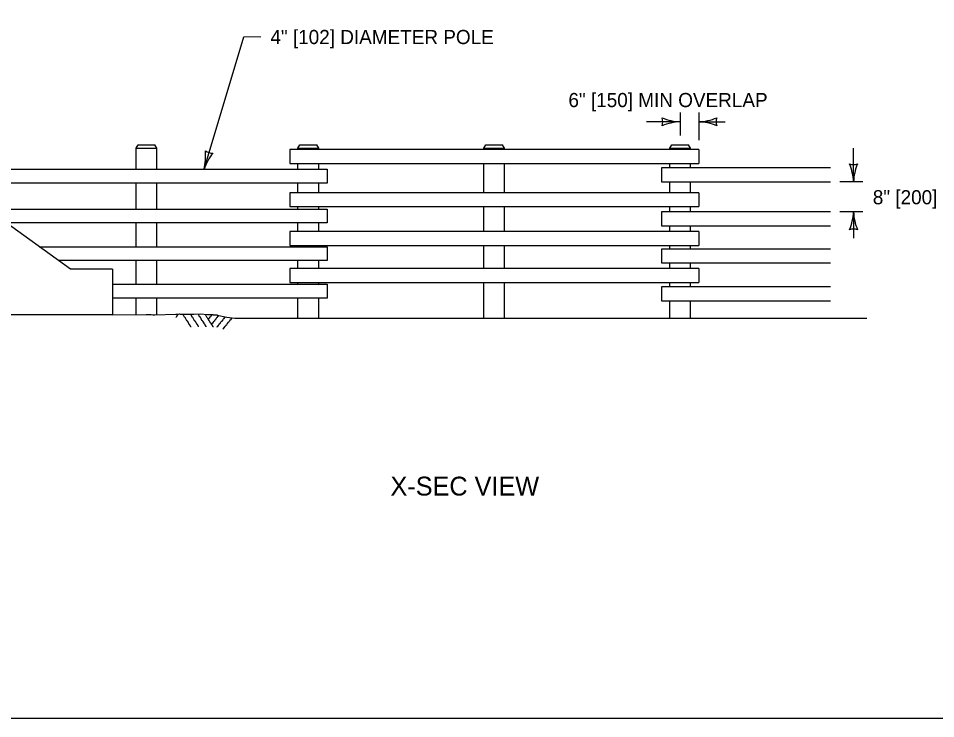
# Model space of a CAD drawing. Extents: x 49991 to 50288, y 49919 to 50011.
# Drawn here: x 50008.695 to 50012.585, y 49987.799 to 49990.769 of the extents above; entities that cross this region are included whole.
import ezdxf

# ---------------------------------------------------------------- set-up
doc = ezdxf.new("R2010")
doc.units = 0
for name, color, linetype in [('Level 1', 7, 'Continuous'), ('Level 2', 7, 'Continuous'), ('Level 3', 7, 'Continuous'), ('Level 5', 7, 'Continuous'), ('Level 7', 7, 'Continuous')]:
    doc.layers.add(name, color=color, linetype=linetype)

msp = doc.modelspace()

# ---------------------------------------------------------------- linework, layer by layer
at = {"layer": 'Level 1'}
for p, q in [((50008.9164, 49989.7045), (50007.5728, 49990.6756)), ((50009.095, 49989.7045), (50008.9164, 49989.7045)), ((50009.095, 49989.7045), (50009.095, 49989.5113)), ((50009.095, 49989.5113), (50007.2424, 49989.5113))]:
    msp.add_line(p, q, dxfattribs=at)
msp.add_lwpolyline([(49999.3835, 49998.9992), (50016.7501, 49998.9992), (50016.7501, 49987.7988), (49999.3835, 49987.7988)], close=True, dxfattribs=at)
msp.add_lwpolyline([(49999.3835, 49998.9992), (50016.7501, 49998.9992), (50016.7501, 49987.7988), (49999.3835, 49987.7988)], close=True, dxfattribs=at)
at = {"layer": 'Level 3'}
for p, q in [((50009.4828, 49990.1289), (50009.6515, 49990.6897)), ((50009.7242, 49990.6896), (50009.6515, 49990.6897)), ((50011.5013, 49990.3701), (50011.5013, 49990.2723)), ((50011.5804, 49990.3701), (50011.5804, 49990.2525)), ((50011.5013, 49990.3301), (50011.3584, 49990.3301)), ((50011.5804, 49990.3301), (50011.6919, 49990.3301)), ((50012.2367, 49990.0755), (50012.2367, 49990.2184)), ((50012.2767, 49990.0755), (50012.1789, 49990.0755)), ((50012.2767, 49989.9482), (50012.1789, 49989.9482)), ((50012.2367, 49989.9482), (50012.2367, 49989.8367))]:
    msp.add_line(p, q, dxfattribs=at)
for centre, radius, start, end in [((50011.5105, 49990.5522), 0.2223, 247.456, 267.6395), ((50011.3731, 49990.3301), 0.0548, 342.1388, 17.8612), ((50011.5128, 49990.0974), 0.233, 92.8273, 112.0772), ((50011.5689, 49990.5628), 0.233, 272.8273, 292.0772), ((50011.5712, 49990.108), 0.2223, 67.456, 87.6395), ((50011.7086, 49990.3301), 0.0548, 162.1388, 197.8612), ((50009.2566, 49990.185), 0.233, 346.0815, 5.3313), ((50009.6929, 49990.0562), 0.2223, 140.7102, 160.8937), ((50009.5197, 49990.2517), 0.0548, 235.393, 271.1153), ((50012.2367, 49990.2037), 0.0548, 252.1388, 287.8612), ((50012.004, 49990.064), 0.233, 2.8273, 22.0772), ((50012.4588, 49990.0663), 0.2223, 157.456, 177.6395), ((50012.0145, 49989.9574), 0.2223, 337.456, 357.6395), ((50012.4694, 49989.9597), 0.233, 182.8273, 202.0772), ((50012.2367, 49989.82), 0.0548, 72.1388, 107.8612)]:
    msp.add_arc(centre, radius, start, end, dxfattribs=at)
at = {"layer": 'Level 5'}
for p, q in [((50009.5112, 49989.5124), (50009.5219, 49989.5124)), ((50009.6129, 49989.4968), (50012.293, 49989.4968))]:
    msp.add_line(p, q, dxfattribs=at)
for points in [[(50009.095, 49989.5113), (50009.2368, 49989.513), (50009.2588, 49989.513), (50009.2655, 49989.5113), (50009.2739, 49989.5113)], [(50009.2739, 49989.5113), (50009.3634, 49989.5146), (50009.3736, 49989.5146), (50009.3786, 49989.5163), (50009.382, 49989.5146), (50009.4343, 49989.5146), (50009.4394, 49989.5146), (50009.4681, 49989.5163), (50009.4968, 49989.513), (50009.5154, 49989.513), (50009.5204, 49989.5113), (50009.5322, 49989.5113), (50009.539, 49989.5113), (50009.539, 49989.5096), (50009.5795, 49989.5011), (50009.6129, 49989.4968)], [(50009.371, 49989.5151), (50009.3727, 49989.5134), (50009.3677, 49989.5066), (50009.3677, 49989.5049), (50009.366, 49989.5049), (50009.3643, 49989.5016), (50009.3631, 49989.5004)], [(50009.3934, 49989.5146), (50009.3985, 49989.5028), (50009.4018, 49989.5011), (50009.4086, 49989.4876), (50009.4103, 49989.4876), (50009.412, 49989.4842), (50009.412, 49989.4826), (50009.4153, 49989.4792), (50009.4187, 49989.4724), (50009.4204, 49989.4724), (50009.4255, 49989.4623), (50009.4289, 49989.4623)], [(50009.4259, 49989.5151), (50009.4309, 49989.5032), (50009.4343, 49989.5016), (50009.4411, 49989.488), (50009.4428, 49989.488), (50009.4445, 49989.4847), (50009.4445, 49989.483), (50009.4478, 49989.4796), (50009.4512, 49989.4729), (50009.4529, 49989.4729), (50009.458, 49989.4627), (50009.4614, 49989.4627)], [(50009.4576, 49989.5159), (50009.4626, 49989.5041), (50009.466, 49989.5024), (50009.4727, 49989.4889), (50009.4744, 49989.4889), (50009.4761, 49989.4855), (50009.4761, 49989.4839), (50009.4795, 49989.4805), (50009.4829, 49989.4737), (50009.4846, 49989.4737), (50009.4896, 49989.4636), (50009.493, 49989.4636)], [(50009.4875, 49989.5142), (50009.4926, 49989.5024), (50009.496, 49989.5007), (50009.5027, 49989.4872), (50009.5044, 49989.4872), (50009.5061, 49989.4839), (50009.5061, 49989.4821), (50009.5095, 49989.4788), (50009.5129, 49989.472), (50009.5145, 49989.472), (50009.5196, 49989.4619), (50009.523, 49989.4619)], [(50009.5159, 49989.5109), (50009.5129, 49989.5079), (50009.5129, 49989.5062), (50009.5111, 49989.5062), (50009.5095, 49989.5029), (50009.5078, 49989.5029), (50009.5078, 49989.5011), (50009.5044, 49989.4978), (50009.5044, 49989.4961), (50009.5027, 49989.4961), (50009.501, 49989.4927)], [(50009.5433, 49989.5068), (50009.542, 49989.5054), (50009.542, 49989.5037), (50009.5403, 49989.5037), (50009.5386, 49989.5003), (50009.5352, 49989.4986), (50009.5335, 49989.4935), (50009.5301, 49989.4919), (50009.5301, 49989.4902), (50009.5267, 49989.4868), (50009.5267, 49989.4851), (50009.5251, 49989.4851), (50009.5234, 49989.4818), (50009.5217, 49989.4818), (50009.5217, 49989.4801), (50009.5183, 49989.4767), (50009.5183, 49989.475), (50009.5166, 49989.475), (50009.5149, 49989.4716)], [(50009.5694, 49989.5032), (50009.5711, 49989.5016), (50009.566, 49989.4948), (50009.566, 49989.4931), (50009.5643, 49989.4931), (50009.5626, 49989.4897), (50009.5576, 49989.4847), (50009.5576, 49989.483), (50009.5559, 49989.483), (50009.5542, 49989.4796), (50009.5508, 49989.4779), (50009.5491, 49989.4729), (50009.5457, 49989.4712), (50009.5457, 49989.4695), (50009.5424, 49989.4661), (50009.5424, 49989.4644), (50009.5407, 49989.4644), (50009.539, 49989.4611), (50009.5373, 49989.4611), (50009.5373, 49989.4594), (50009.5368, 49989.4588)], [(50009.5977, 49989.4986), (50009.5994, 49989.4969), (50009.5943, 49989.4902), (50009.5943, 49989.4885), (50009.5926, 49989.4885), (50009.5909, 49989.4851), (50009.5858, 49989.4801), (50009.5858, 49989.4783), (50009.5842, 49989.4783), (50009.5825, 49989.475), (50009.5791, 49989.4733), (50009.5774, 49989.4682), (50009.574, 49989.4665), (50009.574, 49989.4648), (50009.5707, 49989.4614), (50009.5707, 49989.4598), (50009.569, 49989.4598), (50009.5673, 49989.4564), (50009.5656, 49989.4564), (50009.5656, 49989.4547), (50009.5622, 49989.4513)]]:
    msp.add_lwpolyline(points, dxfattribs=at)
at = {"layer": 'Level 7'}
for p, q in [((50009.1946, 49990.2177), (50009.203, 49990.2323)), ((50009.203, 49990.2323), (50009.2742, 49990.2323)), ((50009.2826, 49990.2177), (50009.2742, 49990.2323)), ((50009.8811, 49990.2177), (50009.8895, 49990.2323)), ((50009.8895, 49990.2323), (50009.9607, 49990.2323)), ((50009.9691, 49990.2177), (50009.9607, 49990.2323)), ((50010.6692, 49990.2177), (50010.6776, 49990.2323)), ((50010.6776, 49990.2323), (50010.7488, 49990.2323)), ((50010.7572, 49990.2177), (50010.7488, 49990.2323)), ((50011.4573, 49990.2177), (50011.4657, 49990.2323)), ((50011.4657, 49990.2323), (50011.5369, 49990.2323)), ((50011.5453, 49990.2177), (50011.5369, 49990.2323)), ((50009.1946, 49990.2177), (50009.2826, 49990.2177)), ((50009.1946, 49990.1289), (50009.1946, 49990.2177)), ((50009.1946, 49990.2125), (50009.1946, 49990.2177)), ((50009.2826, 49990.2125), (50009.2826, 49990.2177)), ((50009.2826, 49990.1289), (50009.2826, 49990.2177)), ((50011.5804, 49990.2125), (50009.846, 49990.2125)), ((50009.846, 49990.2125), (50009.846, 49990.1537)), ((50009.8811, 49990.2177), (50009.9691, 49990.2177)), ((50009.8811, 49990.2125), (50009.8811, 49990.2177)), ((50009.9691, 49990.2125), (50009.9691, 49990.2177)), ((50010.6692, 49990.2177), (50010.7572, 49990.2177)), ((50010.6692, 49990.2125), (50010.6692, 49990.2177)), ((50010.7572, 49990.2125), (50010.7572, 49990.2177)), ((50011.4573, 49990.2177), (50011.5453, 49990.2177)), ((50011.4573, 49990.2125), (50011.4573, 49990.2177)), ((50011.5453, 49990.2125), (50011.5453, 49990.2177)), ((50011.5804, 49990.2125), (50011.5804, 49990.1537)), ((50009.846, 49990.1537), (50011.5804, 49990.1537)), ((50009.8811, 49990.1289), (50009.8811, 49990.1537)), ((50009.9691, 49990.1289), (50009.9691, 49990.1537)), ((50010.6692, 49990.0561), (50010.6692, 49990.1537)), ((50010.7572, 49990.0291), (50010.7572, 49990.1537)), ((50011.4573, 49990.1343), (50011.4573, 49990.1537)), ((50011.5453, 49990.1343), (50011.5453, 49990.1537)), ((50008.3291, 49990.1289), (50010.0042, 49990.1289)), ((50010.0042, 49990.1289), (50010.0042, 49990.0701)), ((50012.1389, 49990.1343), (50011.4222, 49990.1343)), ((50011.4222, 49990.1343), (50011.4222, 49990.0755)), ((50011.4222, 49990.0755), (50012.1389, 49990.0755)), ((50011.4573, 49990.0561), (50011.4573, 49990.0755)), ((50011.5453, 49990.0291), (50011.5453, 49990.0755)), ((50010.0042, 49990.0701), (50008.4105, 49990.0701)), ((50009.1946, 49989.9599), (50009.1946, 49990.0701)), ((50009.1946, 49990.0561), (50009.1946, 49990.0603)), ((50009.2826, 49989.9599), (50009.2826, 49990.0701)), ((50009.8811, 49990.0291), (50009.8811, 49990.0701)), ((50009.8811, 49990.0561), (50009.8811, 49990.0603)), ((50009.9691, 49990.0291), (50009.9691, 49990.0701)), ((50010.6692, 49990.0291), (50010.6692, 49990.0561)), ((50011.4573, 49990.0291), (50011.4573, 49990.0561)), ((50011.5804, 49990.0291), (50009.846, 49990.0291)), ((50009.846, 49990.0291), (50009.846, 49989.9703)), ((50011.5804, 49990.0291), (50011.5804, 49989.9703)), ((50008.563, 49989.9599), (50010.0042, 49989.9599)), ((50009.1946, 49989.9697), (50009.1946, 49989.9703)), ((50009.1946, 49989.9599), (50009.1946, 49989.9703)), ((50009.2826, 49989.9599), (50009.2826, 49989.9703)), ((50009.846, 49989.9703), (50011.5804, 49989.9703)), ((50009.8811, 49989.9697), (50009.8811, 49989.9703)), ((50009.8811, 49989.9599), (50009.8811, 49989.9703)), ((50009.9691, 49989.9599), (50009.9691, 49989.9703)), ((50010.0042, 49989.9599), (50010.0042, 49989.9011)), ((50010.6692, 49989.8648), (50010.6692, 49989.9703)), ((50010.7572, 49989.8648), (50010.7572, 49989.9703)), ((50011.4573, 49989.9482), (50011.4573, 49989.9703)), ((50011.5453, 49989.9482), (50011.5453, 49989.9703)), ((50012.1389, 49989.9482), (50011.4222, 49989.9482)), ((50011.4222, 49989.9482), (50011.4222, 49989.8894)), ((50010.0042, 49989.9011), (50008.6444, 49989.9011)), ((50009.1946, 49989.8004), (50009.1946, 49989.9011)), ((50009.2826, 49989.8004), (50009.2826, 49989.9011)), ((50009.8811, 49989.8648), (50009.8811, 49989.9011)), ((50009.9691, 49989.8648), (50009.9691, 49989.9011)), ((50011.4222, 49989.8894), (50012.1389, 49989.8894)), ((50011.4573, 49989.8648), (50011.4573, 49989.8894)), ((50011.5453, 49989.8648), (50011.5453, 49989.8894)), ((50011.5804, 49989.8648), (50009.846, 49989.8648)), ((50009.846, 49989.8648), (50009.846, 49989.806)), ((50011.5804, 49989.8648), (50011.5804, 49989.806)), ((50009.1946, 49989.8004), (50009.1946, 49989.806)), ((50009.2826, 49989.8004), (50009.2826, 49989.806)), ((50009.846, 49989.806), (50011.5804, 49989.806)), ((50009.8811, 49989.8004), (50009.8811, 49989.806)), ((50009.9691, 49989.8004), (50009.9691, 49989.806)), ((50010.6693, 49989.7076), (50010.6693, 49989.806)), ((50010.7572, 49989.7333), (50010.7572, 49989.806)), ((50011.4574, 49989.7903), (50011.4574, 49989.806)), ((50011.5453, 49989.7903), (50011.5453, 49989.806)), ((50008.7837, 49989.8004), (50010.0042, 49989.8004)), ((50010.0042, 49989.8004), (50010.0042, 49989.7416)), ((50012.1389, 49989.7903), (50011.4222, 49989.7903)), ((50011.4222, 49989.7903), (50011.4222, 49989.7315)), ((50010.0042, 49989.7416), (50008.865, 49989.7416)), ((50009.1946, 49989.6412), (50009.1946, 49989.7416)), ((50009.2826, 49989.6412), (50009.2826, 49989.7416)), ((50009.8811, 49989.7076), (50009.8811, 49989.7416)), ((50009.9691, 49989.7076), (50009.9691, 49989.7416)), ((50010.7572, 49989.7076), (50010.7572, 49989.7333)), ((50011.4222, 49989.7315), (50012.1389, 49989.7315)), ((50011.4574, 49989.7076), (50011.4574, 49989.7315)), ((50011.5453, 49989.7076), (50011.5453, 49989.7333)), ((50011.5804, 49989.7076), (50009.846, 49989.7076)), ((50009.846, 49989.7076), (50009.846, 49989.6487)), ((50011.5804, 49989.7076), (50011.5804, 49989.6487)), ((50009.1946, 49989.6412), (50009.1946, 49989.6487)), ((50009.2826, 49989.6412), (50009.2826, 49989.6487)), ((50009.846, 49989.6487), (50011.5804, 49989.6487)), ((50009.8811, 49989.6412), (50009.8811, 49989.6487)), ((50009.9691, 49989.6412), (50009.9691, 49989.6487)), ((50010.6694, 49989.4968), (50010.6693, 49989.6487)), ((50010.7572, 49989.4968), (50010.7572, 49989.6487)), ((50011.4574, 49989.6302), (50011.4574, 49989.6487)), ((50011.5453, 49989.6302), (50011.5453, 49989.6487)), ((50009.095, 49989.6412), (50010.0042, 49989.6412)), ((50010.0042, 49989.6412), (50010.0042, 49989.5824)), ((50012.1389, 49989.6302), (50011.4222, 49989.6302)), ((50011.4222, 49989.6302), (50011.4222, 49989.5713)), ((50010.0042, 49989.5824), (50009.095, 49989.5824)), ((50009.1946, 49989.512), (50009.1946, 49989.5824)), ((50009.2826, 49989.5109), (50009.2826, 49989.5824)), ((50009.8811, 49989.4968), (50009.8811, 49989.5824)), ((50009.9691, 49989.5295), (50009.9691, 49989.5824)), ((50011.4222, 49989.5713), (50012.1389, 49989.5713)), ((50011.4575, 49989.4971), (50011.4574, 49989.5713)), ((50011.5453, 49989.4968), (50011.5453, 49989.5713)), ((50009.9691, 49989.4968), (50009.9691, 49989.5295))]:
    msp.add_line(p, q, dxfattribs=at)

# ---------------------------------------------------------------- texts
at = {"layer": 'Level 2'}
for s, height, p in [('4" [102] DIAMETER POLE', 0.06, (50009.7642, 49990.6596)), ('6" [150] MIN OVERLAP', 0.06, (50011.0278, 49990.3923)), ('8" [200] MAX SPACING', 0.06, (50012.3185, 49989.9801)), ('X-SEC VIEW', 0.08, (50010.2734, 49988.745))]:
    msp.add_text(s, height=height, dxfattribs=at).set_placement(p)

doc.saveas('drawing.dxf')
